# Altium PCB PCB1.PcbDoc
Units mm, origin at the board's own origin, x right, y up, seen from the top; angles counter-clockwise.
Board outline 98.04 x 89.53 mm, 2 copper layers (Top Layer, Bottom Layer); 31 components, 20 nets, 121 pads, 3 vias.
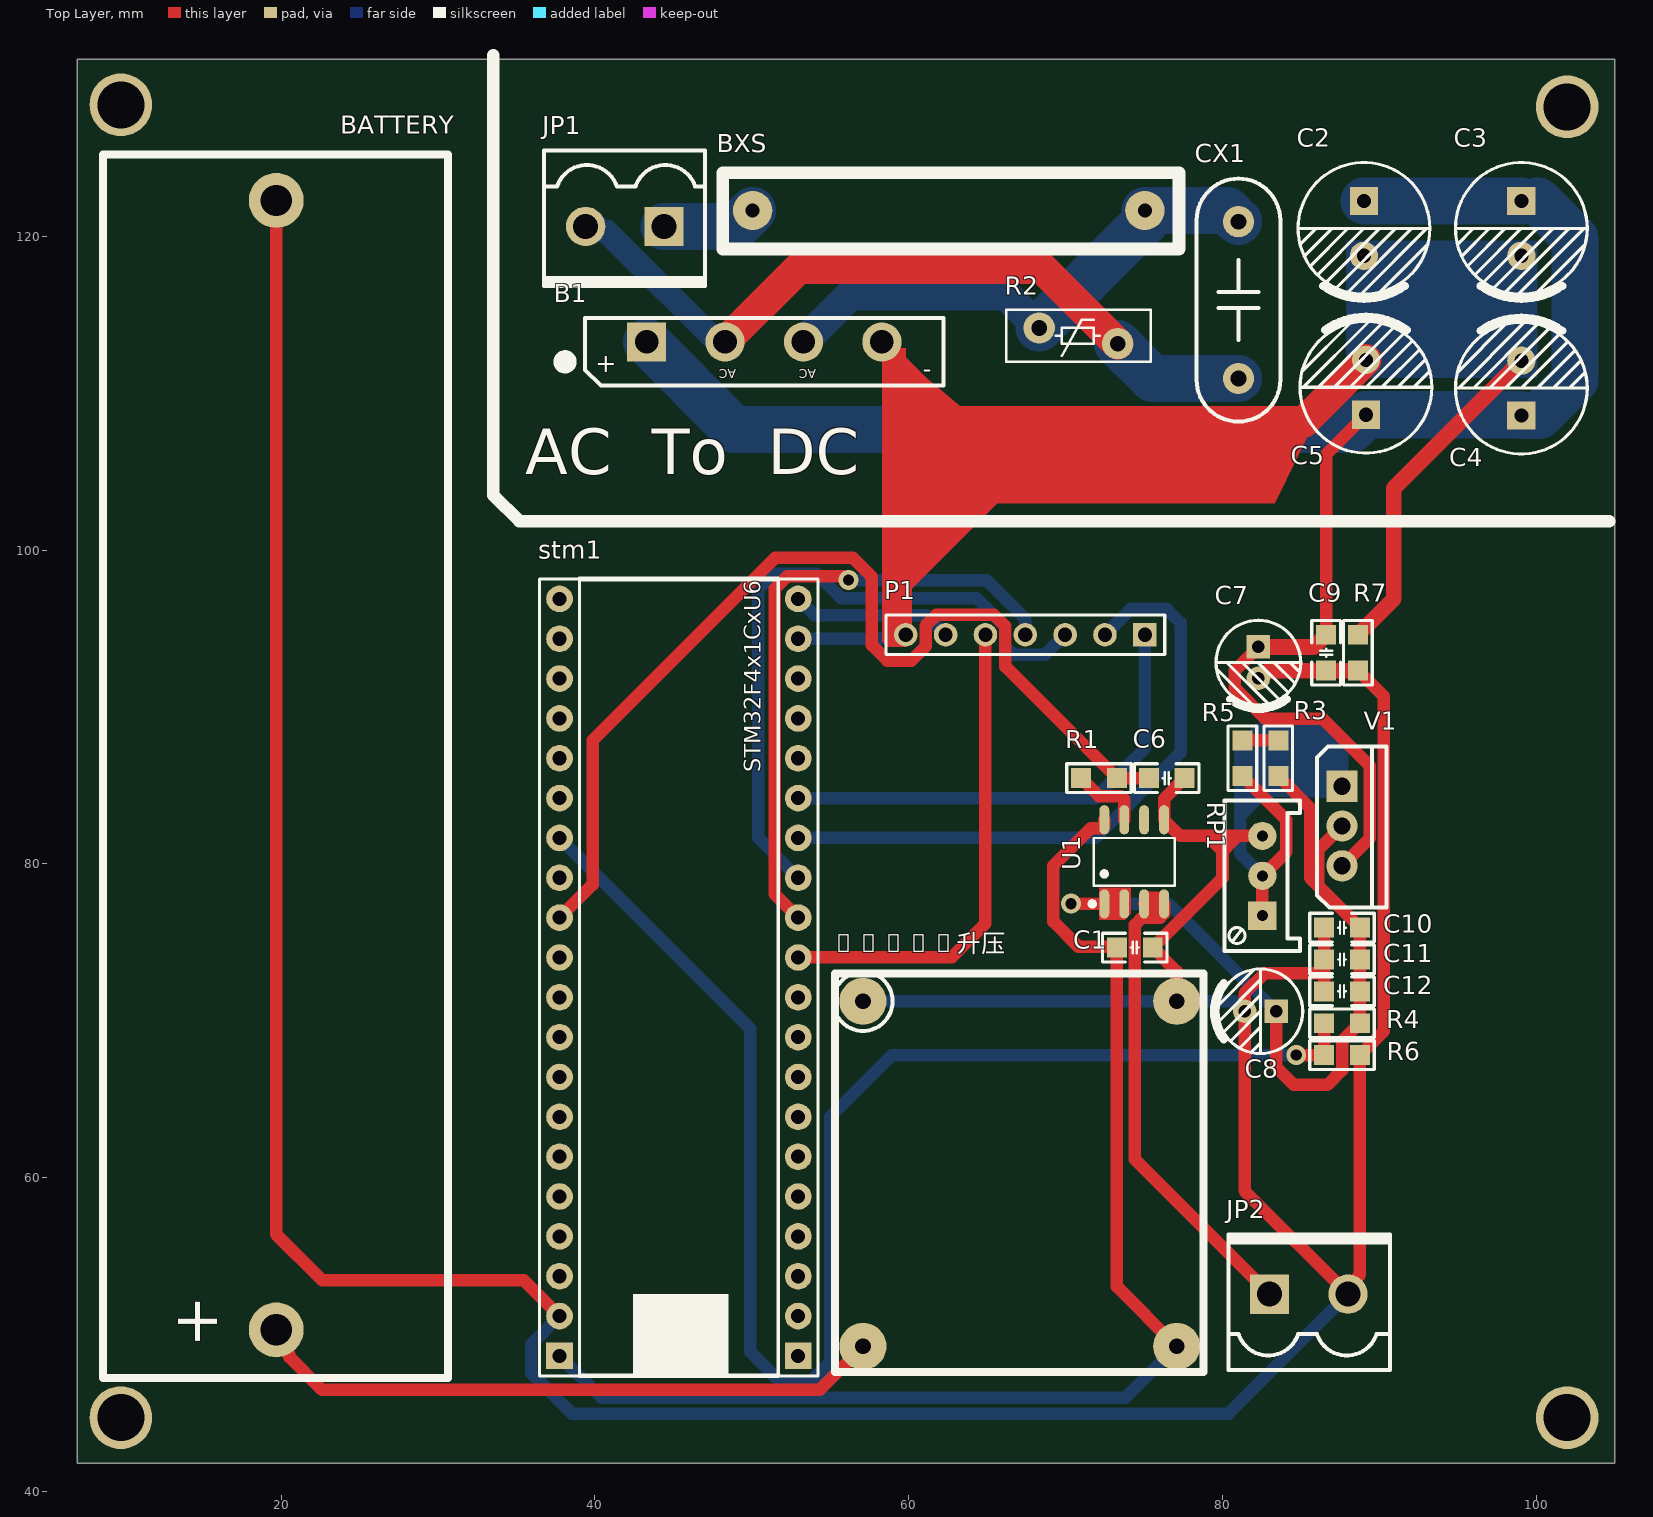
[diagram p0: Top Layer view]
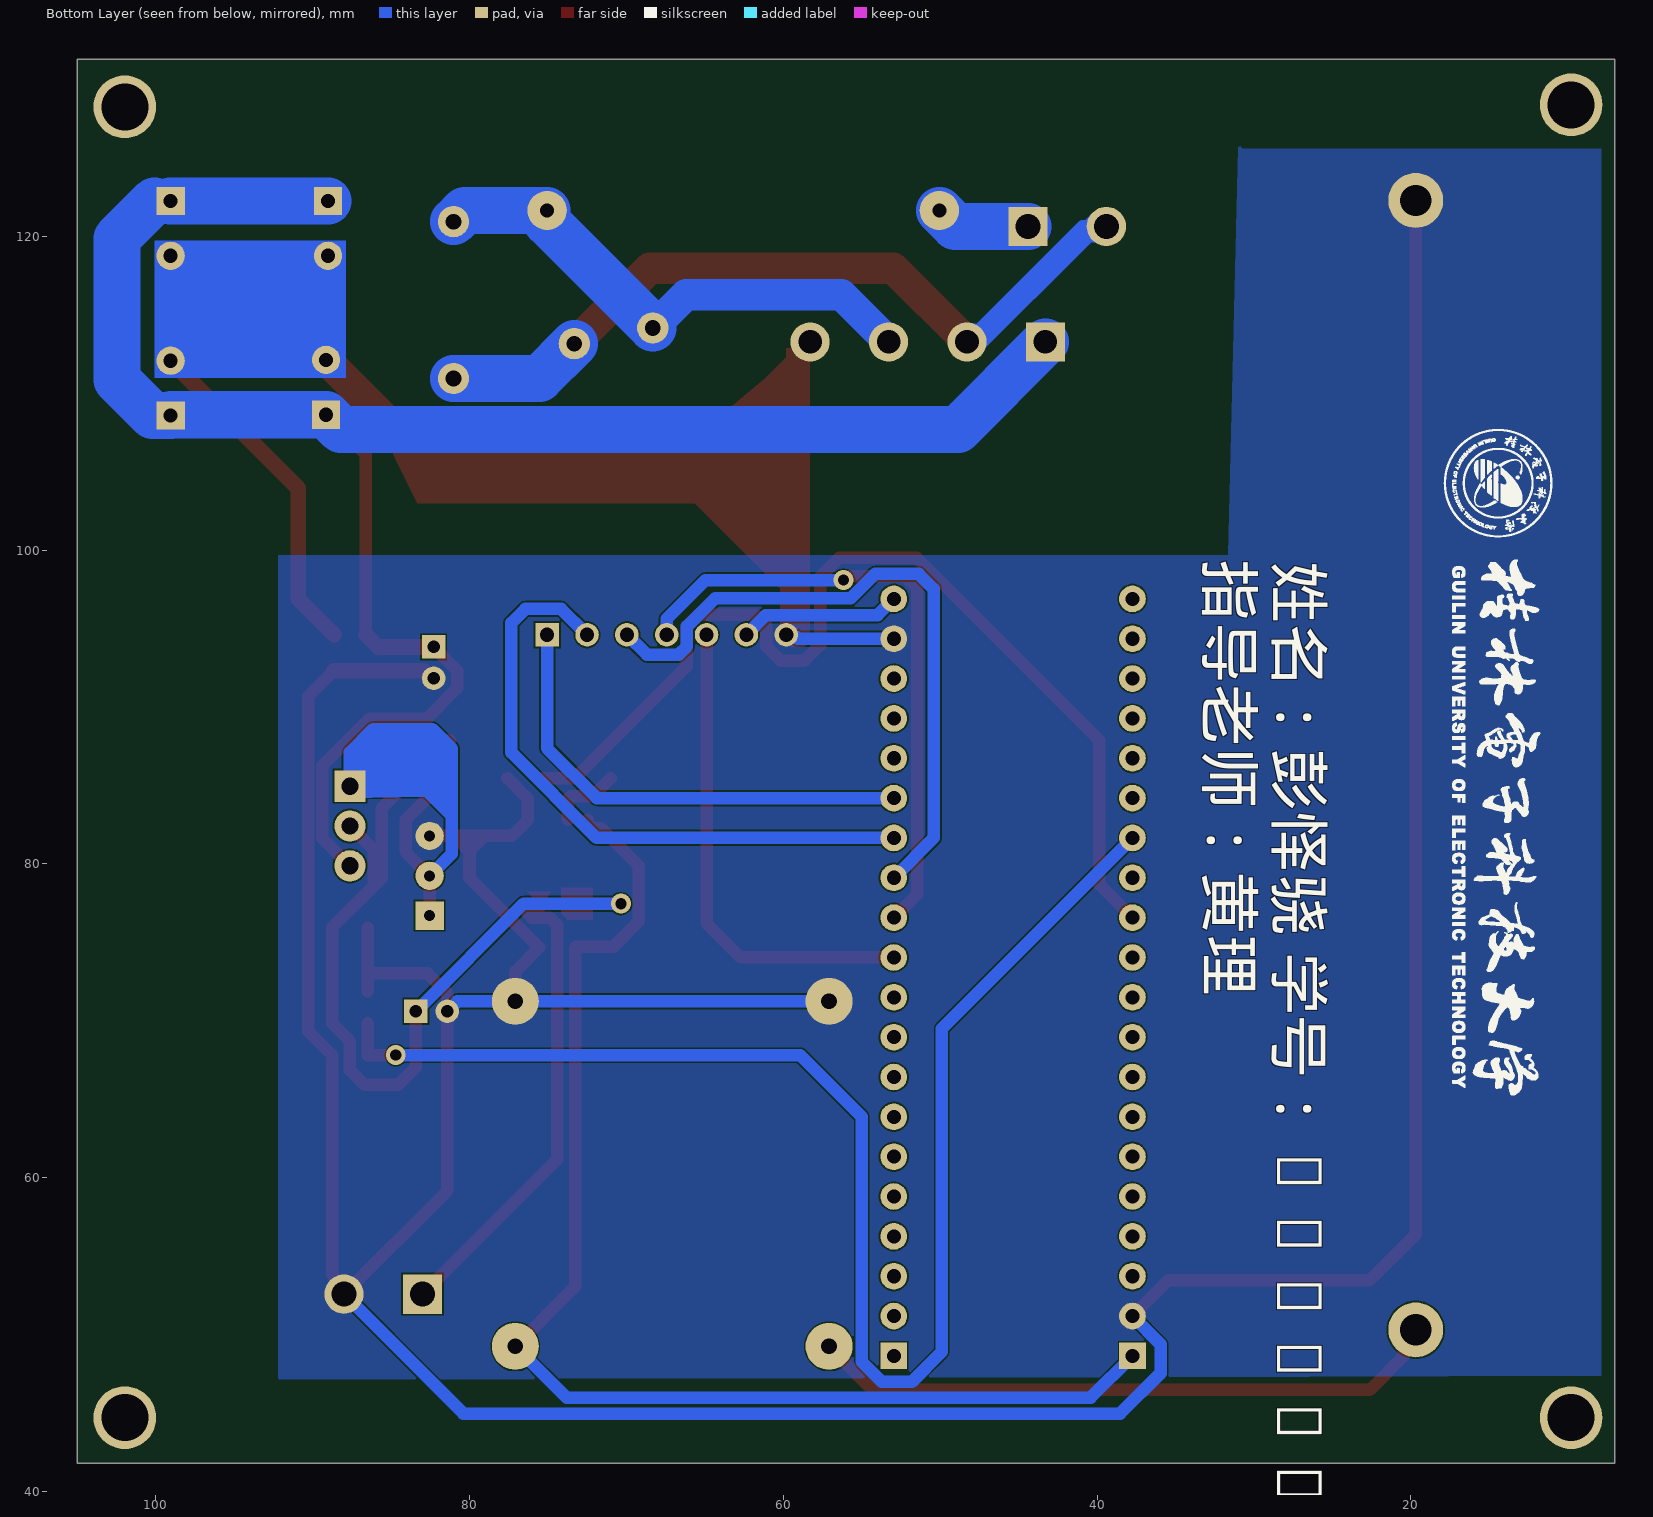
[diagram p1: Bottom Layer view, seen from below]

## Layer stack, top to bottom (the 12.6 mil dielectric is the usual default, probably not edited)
Top Solder: solder mask 0.0102, Solder Resist, Dk 3.5
Top Layer: signal copper 0.0356
Dielectric 1: dielectric 0.32, FR-4, Dk 4.8
Bottom Layer: signal copper 0.0356
Bottom Solder: solder mask 0.0102, Solder Resist, Dk 3.5

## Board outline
6.985,41.783 6.985,131.318 105.029,131.318 105.029,41.783

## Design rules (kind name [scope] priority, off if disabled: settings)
Clearance [All] p1: gap=0.1 ignorepadtopadclearanceinfootprint=FALSE
PlaneClearance [All] p1: clearance=0.8
PolygonConnect [All] p1: connectstyle=Direct reliefconductorwidth=0.254 reliefentries=4 polygonreliefangle="90 Angle" airgapwidth=0.254
RoutingVias [All] p1: holewidth=0.711 width=1.27 viastyle="Through Hole" minholewidth=0.711 minwidth=1.27 maxholewidth=0.711 maxwidth=1.27
SolderMaskExpansion [All] p1: expansion=0.102 istentingtop=FALSE
Width [All] p1: maxlimit=6 minlimit=0.254 preferedwidth=0.8
29 further rules are at their usual default settings.

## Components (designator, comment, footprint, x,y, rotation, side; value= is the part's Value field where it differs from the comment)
B1 "DB" GBU 50.793,113.284 r180 top
BATTERY "BAT" BAT 19.685,50.301 r90 top (schematic designator *3)
BOOST升压 "Boost" Boost 57.089,71.247 r0 top (schematic designator *2)
BXS "bxs" bxs 50.057,121.666 r0 top (schematic designator *1)
C1 "104" "C 0805_M" 74.422,74.676 r180 top
C2 "470uF" "CAP 3.5*8*11.5" 89.027,120.523 r270 top
C3 "100uF" "CAP 3.5*8*11.5" 99.06,120.523 r270 top
C4 "470uF" "CAP 3.5*8*11.5" 99.06,110.335 r90 top
C5 "100uF" "CAP 3.5*8*11.5" 89.154,110.391 r90 top
C6 "104" "C 0805_M" 76.454,85.471 r0 top
C7 "10uF" "CAP 2.0*5*11" 82.296,92.837 r270 top
C8 "10uF" "CAP 2.0*5*11" 82.423,70.612 r180 top
C9 "104" "C 0805_M" 86.614,93.472 r90 top
C10 "104" "C 0805_M" 87.63,75.946 r0 top
C11 "104" "C 0805_M" 87.63,73.914 r0 top
C12 "104" "C 0805_M" 87.63,71.882 r0 top
CX1 "0.1uF/275V" "CX 10*13*11" 81.026,115.951 r90 top
JP1 "HDR-1X2" KF2EDGK5.0-LI-2P 41.91,120.65 r180 top
JP2 "HDR-1X2" KF2EDGK5.0-LI-2P 85.511,52.578 r0 top
P1 "Header 7" HDR1X7 75.057,94.615 r180 top
R1 "220" "R 0805_M" 72.136,85.471 r180 top
R2 "471K" "VDR 9D-4.5" 73.326,113.673 r180 top
R3 "220" "R 0805_M" 83.566,86.741 r270 top
R4 "51K" "R 0805_M" 87.63,69.85 r0 top
R5 "22" "R 0805_M" 81.28,86.741 r90 top
R6 "10K" "R 0805_M" 87.63,67.818 r180 top
R7 "220" "R 0805_M" 88.646,93.472 r90 top
RP1 "10K" 3296W 82.55,79.248 r90 top
stm1 "U?" stm32f4x1cxu6_core 45.974,73.025 r90 top
U1 "CC6902SO-5A" SOP-8_L4.9-W3.9-P1.27-LS6.0-BL 74.295,80.137 r0 top
V1 "LM317" TO220A 87.63,82.423 r270 top

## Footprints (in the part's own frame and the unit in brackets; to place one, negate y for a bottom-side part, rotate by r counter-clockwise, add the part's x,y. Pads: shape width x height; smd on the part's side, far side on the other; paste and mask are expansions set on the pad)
3296W [mm] "Precise Multi-Winding Adjustable Resistor"
  rect 1.8x1.8 hole 0.7: 1(-2.54,0)
  round 1.8 hole 0.7: 2(0,0) 3(2.54,0)
  silkscreen extent -4.8,-2.4 4.8,2.4, body extent -4.75,-2.4 4.75,2.4, height 11.52
BAT [mm]
  round 3.5 hole 2: 1(0,0) 2(72,0)
  silkscreen extent -3.07,-10.95 74.93,11.05
Boost [mm]
  round 3 hole 1: 1(0,0) 2(0,-22) 3(20,-22) 4(20,0)
  silkscreen extent -1.89,-23.62 21.72,1.88
bxs [mm]
  round 2.5 hole 0.889: 1(0,0) 2(25,0)
  silkscreen extent -1.91,-2.46 27.18,2.41
"C 0805_M" [mil] "无极性贴片电容"
  rect 50x50 smd: 1(-45,0) 2(45,0)
  silkscreen extent -81,-36 81,36, body extent -39,-24 39,24, height 20
"CAP 2.0*5*11" [mm] "脚距2mm直径5mm高度11mm"
  rect 1.5x1.5 hole 0.8: 1(-1,0)
  round 1.5 hole 0.8: 2(1,0)
  silkscreen extent -2.7,-2.7 2.96,2.7, body extent -2.5,-2.5 2.51,2.5, height 11.04
"CAP 3.5*8*11.5" [mm] "脚距3.5mm直径8mm高度11.5mm"
  rect 1.8x1.8 hole 0.9: 1(-1.75,0)
  round 1.8 hole 0.9: 2(1.75,0)
  silkscreen extent -4.2,-4.2 4.5,4.2, body extent -4,-4 4.01,4, height 11.53
"CX 10*13*11" [mm] "脚距10mm高13mm厚11mmhttps://item.taobao.com/item.htm?ft=t&id=613637044352"
  round 2 hole 1: 1(-5,0) 2(5,0)
  silkscreen extent -7.75,-2.67 7.75,2.67, body extent -6.5,-2.5 6.5,2.5, height 11.02
GBU [mm] "整流桥，脚距：5mm/200mil  https://item.taobao.com/item.htm?ft=t&id=613637044352"
  round 2.5 hole 1.5: AC1(-2.5,0) AC2(2.5,0) DC-(-7.5,0)
  rect 2.5x2.5 hole 1.5: DC+(7.5,0)
  silkscreen extent -11.43,-1.52 13.06,2.79, body extent -11,-1.15 11,2.35, height 20.8
HDR1X7 [mm] "Connector; Header; 7 Position"
  rect 1.5x1.5 hole 0.9: 1(0,0)
  round 1.5 hole 0.9: 2(2.54,0) 3(5.08,0) 4(7.62,0) 5(10.16,0) 6(12.7,0) 7(15.24,0)
  silkscreen extent -1.27,-1.27 16.51,1.27
KF2EDGK5.0-LI-2P [mm] "立插端子"
  rect 2.5x2.5 hole 1.6: 1(-2.5,0)
  round 2.5 hole 1.6: 2(2.5,0)
  silkscreen extent -5.12,-4.83 5.17,3.81, body extent -5.04,-4.75 5.04,3.75, height 11.25
"R 0805_M" [mil] "1/8W贴片电阻"
  rect 50x50 smd: 1(-45,0) 2(45,0)
  silkscreen extent -81,-36 81,36, body extent -39,-25 39,25, height 20
SOP-8_L4.9-W3.9-P1.27-LS6.0-BL [mm]
  oval 0.63x1.865 smd: 1(-1.82,-2.682) 2(-0.55,-2.682) 3(0.72,-2.682) 4(1.99,-2.682) 5(1.99,2.682) 6(0.72,2.682) 7(-0.55,2.682) 8(-1.82,2.682)
  silkscreen extent -2.74,-2.83 2.66,1.52
stm32f4x1cxu6_core [mm]
  rect 1.7x1.7 hole 0.9: 1(-24.384,-6.985) 40(-24.384,8.23)
  round 1.7 hole 0.9: 2(-21.844,-6.985) 3(-19.304,-6.985) 4(-16.764,-6.985) 5(-14.224,-6.985) 6(-11.684,-6.985) 7(-9.144,-6.985) 8(-6.604,-6.985) 9(-4.064,-6.985) 10(-1.524,-6.985) 11(1.016,-6.985) 12(3.556,-6.985) 13(6.096,-6.985) 14(8.636,-6.985) 15(11.176,-6.985) 16(13.716,-6.985) 17(16.256,-6.985) 18(18.796,-6.985) 19(21.336,-6.985) 20(23.876,-6.985) 21(23.876,8.23) 22(21.336,8.23) 23(18.796,8.23) 24(16.256,8.23) 25(13.716,8.23) 26(11.176,8.23) 27(8.636,8.23) 28(6.096,8.23) 29(3.556,8.23) 30(1.016,8.23) 31(-1.524,8.23) 32(-4.064,8.23) 33(-6.604,8.23) 34(-9.144,8.23) 35(-11.684,8.23) 36(-14.224,8.23) 37(-16.764,8.23) 38(-19.304,8.23) 39(-21.844,8.23)
  silkscreen extent -25.65,-8.26 25.15,9.5
TO220A [mm] "220，3脚晶体管"
  rect 2x2 hole 1.1: 1(-2.54,0)
  round 2 hole 1.1: 2(0,0) 3(2.54,0)
  silkscreen extent -5.08,-1.6 5.21,2.82, body extent -5.15,-1.53 5.15,2.9, height 18.5
"VDR 9D-4.5" [mm] "压敏电阻9mm*4.5mm(直径*厚度）https://item.taobao.com/item.htm?ft=t&id=613637044352"
  round 2 hole 1: 1(0,0.5) 2(5,-0.5)
  silkscreen extent -2.11,-1.65 7.11,1.65, body extent -2,-1.5 7,1.5, height 10

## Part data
B1: "整流桥"
C1 C6 C9 C10 C11 C12: library part C, "贴片电容"
C2 C3 C4 C5 C7 C8: library part CE, "直插电解电容"
CX1: library part CX, "安规X电容"
JP1 JP2: library part "Header 2", "2P接插件"
P1: "Header, 7-Pin"
R1 R3 R4 R5 R6 R7: library part R, "贴片电阻"
R2: library part R_VSR, "压敏电阻"
RP1: library part RP, "单联电位器"
stm1: library part stm32f4x1cxu6_core
V1: "可调线性稳压芯片"

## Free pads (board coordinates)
  round 4 hole 3: 3(9.779,128.397) 4(9.779,44.704) 5(101.981,128.27) 6(101.981,44.704)

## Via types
v1: diameter 1.27, hole 0.711, Top Layer to Bottom Layer, 3 vias

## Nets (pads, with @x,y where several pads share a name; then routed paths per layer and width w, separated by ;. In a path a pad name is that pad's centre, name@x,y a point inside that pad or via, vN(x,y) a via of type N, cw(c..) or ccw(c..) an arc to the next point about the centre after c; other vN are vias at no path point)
+5: BOOST升压.3 C1.2 stm1.40 U1.8 | length 81.8
  Top Layer w0.8: U1.8 72.475,82.372 72.39,82.287 71.619,82.287 69.223,79.891 69.223,76.319 70.817,74.725 73.23,74.725 C1.2 73.279,53.057 BOOST升压.3
  Bottom Layer w0.8: stm1.40 40.411,45.974 73.816,45.974 BOOST升压.3
A_ACD: C6.1 R1.1 stm1.29 | length 65.5
  Top Layer w0.8: stm1.29 39.853,78.689 39.853,87.884 51.486,99.517 56.439,99.517 57.658,98.298 57.658,93.955 58.649,92.964 60.173,92.964 61.087,93.878 61.087,95.199 61.773,95.885 65.43,95.885 66.167,95.148 66.167,92.583 R1.1 C6.1
BAT: BATTERY.1 BOOST升压.2 | length 40.7
  Top Layer w0.8: BATTERY.1 19.685,49.57 20.522,48.733 20.522,48.566 22.606,46.482 54.324,46.482 BOOST升压.2
CS: P1.1 stm1.15 | length 30.7
  Bottom Layer w0.8: stm1.15 71.882,84.201 75.057,87.376 P1.1
D0: P1.5 stm1.11 | length 31.2
  Top Layer w0.8: stm1.11 62.738,74.041 64.897,76.2 P1.5
D1: P1.4 stm1.12 | length 40
  Top Layer w0.8: stm1.12 51.46,78.08 51.46,97.536 52.273,98.349 55.783,98.349 56.037,98.095 v1(56.164,98.095)
  Bottom Layer w0.8: v1(56.164,98.095) 64.974,98.095 67.437,95.632 P1.4
DC: P1.2 stm1.14 | length 40.8
  Bottom Layer w0.8: stm1.14 71.907,81.661 77.343,87.097 77.343,95.377 76.454,96.266 74.168,96.266 P1.2
GND: B1.DC- BATTERY.2 BOOST升压.1 BOOST升压.4 C1.1 C2.2 C3.2 C4.2 C5.2 C6.2 C7.2 C8.2 C9.1 C10.1 C11.1 C12.1 JP2.2 P1.7 R6.1 R7.1 R7.2 RP1.3 stm1.19 stm1.39 U1.5 | length 354.2
  Top Layer w0.8: BATTERY.2 19.685,56.388 22.606,53.467 35.458,53.467 stm1.39 ; B1.DC- 59.817,111.76 ; P1.7 59.817,111.76 ; 63.38,108.197 59.817,111.76 ; BOOST升压.4 77.089,73.152 C1.1 80.01,79.121 80.01,81.788 ; 77.216,81.889 U1.5 76.285,84.159 C6.2 ; 77.317,81.788 80.01,81.788 ; RP1.3 80.01,81.788 ; C12.1 86.487,73.025 ; C10.1 C11.1 86.487,73.025 ; R7.1 90.297,90.678 90.297,69.342 R6.1 88.773,53.8 88.011,53.038 JP2.2 81.423,59.166 81.423,71.771 82.677,73.025 86.487,73.025
  Top Layer w1: C7.2 82.431,91.837 82.923,92.329 C9.1 R7.1 ; R7.2 90.932,96.901 90.932,103.957 C4.2
  Top Layer w2: 63.38,108.197 85.21,108.197 C5.2
  Bottom Layer w0.8: stm1.39 35.941,49.378 35.941,47.549 38.532,44.958 80.391,44.958 JP2.2 ; stm1.19 59.068,94.361 59.188,94.481 59.683,94.481 P1.7 ; BOOST升压.1 BOOST升压.4 80.788,71.247 C8.2
LM317_Out_1: C8.1 C10.2 C11.2 C12.2 R3.2 R4.2 U1.1 U1.2 V1.2 | length 53.7
  Top Layer w0.8: v1(70.358,77.47) 70.366,77.462 72.467,77.462 U1.1 U1.2 ; C8.1 83.423,67.054 84.564,65.913 86.69,65.913 87.63,66.853 87.63,68.707 R4.2 C12.2 C11.2 C10.2 86.106,78.613 ; R3.2 85.598,83.566 85.598,79.121 86.106,78.613 ; V1.2 86.106,80.899 86.106,78.613
  Bottom Layer w0.8: v1(70.358,77.47) 76.565,77.47 C8.1
LM317_Out_2: JP2.1 U1.3 U1.4 | length 31.3
  Top Layer w0.8: U1.3 75.269,77.455 76.01,77.003 U1.4@76.285,76.835 ; U1.4 U1.4@76.285,76.835 ; JP2.1 74.422,61.167 74.422,76.112 74.891,76.581 76.031,76.581 U1.4@76.285,76.835
Net*1_1: BXS.1 JP1.1 | length 6.1
  Bottom Layer w3: JP1.1 49.041,120.65 BXS.1
Net*1_2: B1.AC1 BXS.2 CX1.2 R2.2 | length 33.7
  Bottom Layer w2: B1.AC1 56.297,116.288 66.211,116.288 R2.2
  Bottom Layer w3: R2.2 75.057,120.904 BXS.2 80.311,121.666 CX1.2
NetB1_AC2: B1.AC2 CX1.1 JP1.2 R2.1 | length 49.5
  Top Layer w2: B1.AC2 52.992,117.983 68.516,117.983 R2.1
  Bottom Layer w0.8: JP1.2 40.927,120.65 B1.AC2
  Bottom Layer w3: R2.1 75.548,110.951 CX1.1
NetP1_6: P1.6 stm1.20 | length 10.3
  Bottom Layer w0.8: stm1.20 53.995,95.865 61.107,95.865 P1.6
NetR1_2: R1.2 U1.7 | length 4.6
  Top Layer w0.8: R1.2 72.136,84.328 73.542,84.328 73.745,84.125 U1.7
NetR3_1: R3.1 R5.2 | length 2.3
  Top Layer w0.8: R5.2 R3.1
NetR5_1: R5.1 RP1.1 RP1.2 V1.1 | length 29.2
  Top Layer w0.8: R5.1 84.074,82.804 84.074,80.772 RP1.2 RP1.1
  Bottom Layer w0.8: RP1.2 81.128,80.67 81.128,87.351 82.372,88.595 86.157,88.595 87.63,87.122 V1.1
RES: P1.3 stm1.13 | length 42.8
  Bottom Layer w0.8: stm1.13 50.419,81.661 50.419,97.536 51.384,98.501 54.153,98.501 55.702,96.952 64.338,96.952 66.147,95.143 66.147,93.868 66.67,93.345 68.707,93.345 P1.3
V_ACD: R4.1 R6.2 stm1.27 | length 95
  Top Layer w0.8: v1(84.709,67.818) R6.2 R4.1
  Bottom Layer w0.8: stm1.27 49.911,69.494 49.911,48.895 51.816,46.99 53.721,46.99 54.991,48.26 54.991,63.881 58.928,67.818 v1(84.709,67.818)
VCC: B1.DC+ C2.1 C3.1 C4.1 C5.1 C7.1 C9.2 V1.3 | length 127.1
  Top Layer w0.8: C7.1 80.792,92.333 80.792,91.214 82.733,89.273 86.386,89.273 89.384,86.275 89.384,81.637 V1.3 ; C9.2 86.614,106.101 C5.1
  Top Layer w1: C7.1 85.836,93.837 C9.2
  Bottom Layer w2: C3.1 100.104,122.273
  Bottom Layer w3: B1.DC+ 48.88,107.697 88.21,107.697 C5.1 99.004,108.641 C4.1 100.203,108.585 102.489,110.871 102.489,119.888 100.104,122.273 ; C2.1 C3.1
pads on no net: stm1.1 stm1.2 stm1.3 stm1.4 stm1.5 stm1.6 stm1.7 stm1.8 stm1.9 stm1.10 stm1.16 stm1.17 stm1.18 stm1.21 stm1.22 stm1.23 stm1.24 stm1.25 stm1.26 stm1.28 stm1.30 stm1.31 stm1.32 stm1.33 stm1.34 stm1.35 stm1.36 stm1.37 stm1.38 U1.6

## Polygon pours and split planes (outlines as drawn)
GND on Bottom Layer "GND_L02_P001" (solid, pour order 1): 30.988,125.857 30.734,125.603 7.874,125.603 7.874,47.371 8.382,47.371 8.763,47.371 92.202,47.117 92.202,99.695 90.424,99.695 31.623,99.695

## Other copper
Top Layer:
  rectangle net GND: 58.293,94.234 59.817,112.903
  region net GND: 58.293,94.234 58.674,93.853 59.817,93.853 59.817,94.107 60.198,94.488
  region net GND: 83.338,102.997 65.659,102.997 59.817,97.155 59.817,108.839 84.074,108.839 85.493,107.42
  region net GND: 78.613,81.534 78.74,81.534 80.01,80.264 81.28,81.534 81.28,81.788
  region net LM317_Out_2: 74.803,78.232 76.327,78.232 76.031,77.936 76.031,76.581
  region net LM317_Out_1: 72.136,78.486 74.168,78.486 74.168,76.835 73.787,76.454 72.136,76.454
  region net GND: 62.865,108.458 63.856,107.798 60.007,103.95 59.937,104.02 59.937,109.848
  region net GND: 59.944,110.744 59.817,110.617 59.817,107.823 63.754,107.823 64.294,108.363 60.79,111.252 59.944,111.252
Bottom Layer:
  rectangle net GND: 87.884,110.998 100.076,119.761
  region net NetR5_1: 83.058,84.455 81.407,82.804 81.407,84.455 80.899,84.963
  region net NetR5_1: 87.884,84.201 87.884,86.741 86.157,88.468 86.157,88.595 82.372,88.595 81.128,87.351 81.128,84.353 81.153,84.328
  region net NetB1_AC2: 38.862,119.634 40.386,119.634 47.625,112.395 48.768,113.538 48.768,114.427 47.371,114.427 40.386,121.412

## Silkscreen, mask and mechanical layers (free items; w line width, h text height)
Top Overlay:
  lines w0.8: 33.528,131.572 33.528,103.505 35.179,101.854 104.648,101.854
  text "AC  To  DC" at 35.56,103.886 h5
Bottom Overlay:
  drawing of 19101 lines, arcs and shapes, not listed
  text "指导老师：黄理" at 33.909,99.441 h5 r90
  text "姓名：彭怿骁 学号：201202060116" at 29.464,99.314 h5 r90
Mechanical 1:
  the board outline again, w0.8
